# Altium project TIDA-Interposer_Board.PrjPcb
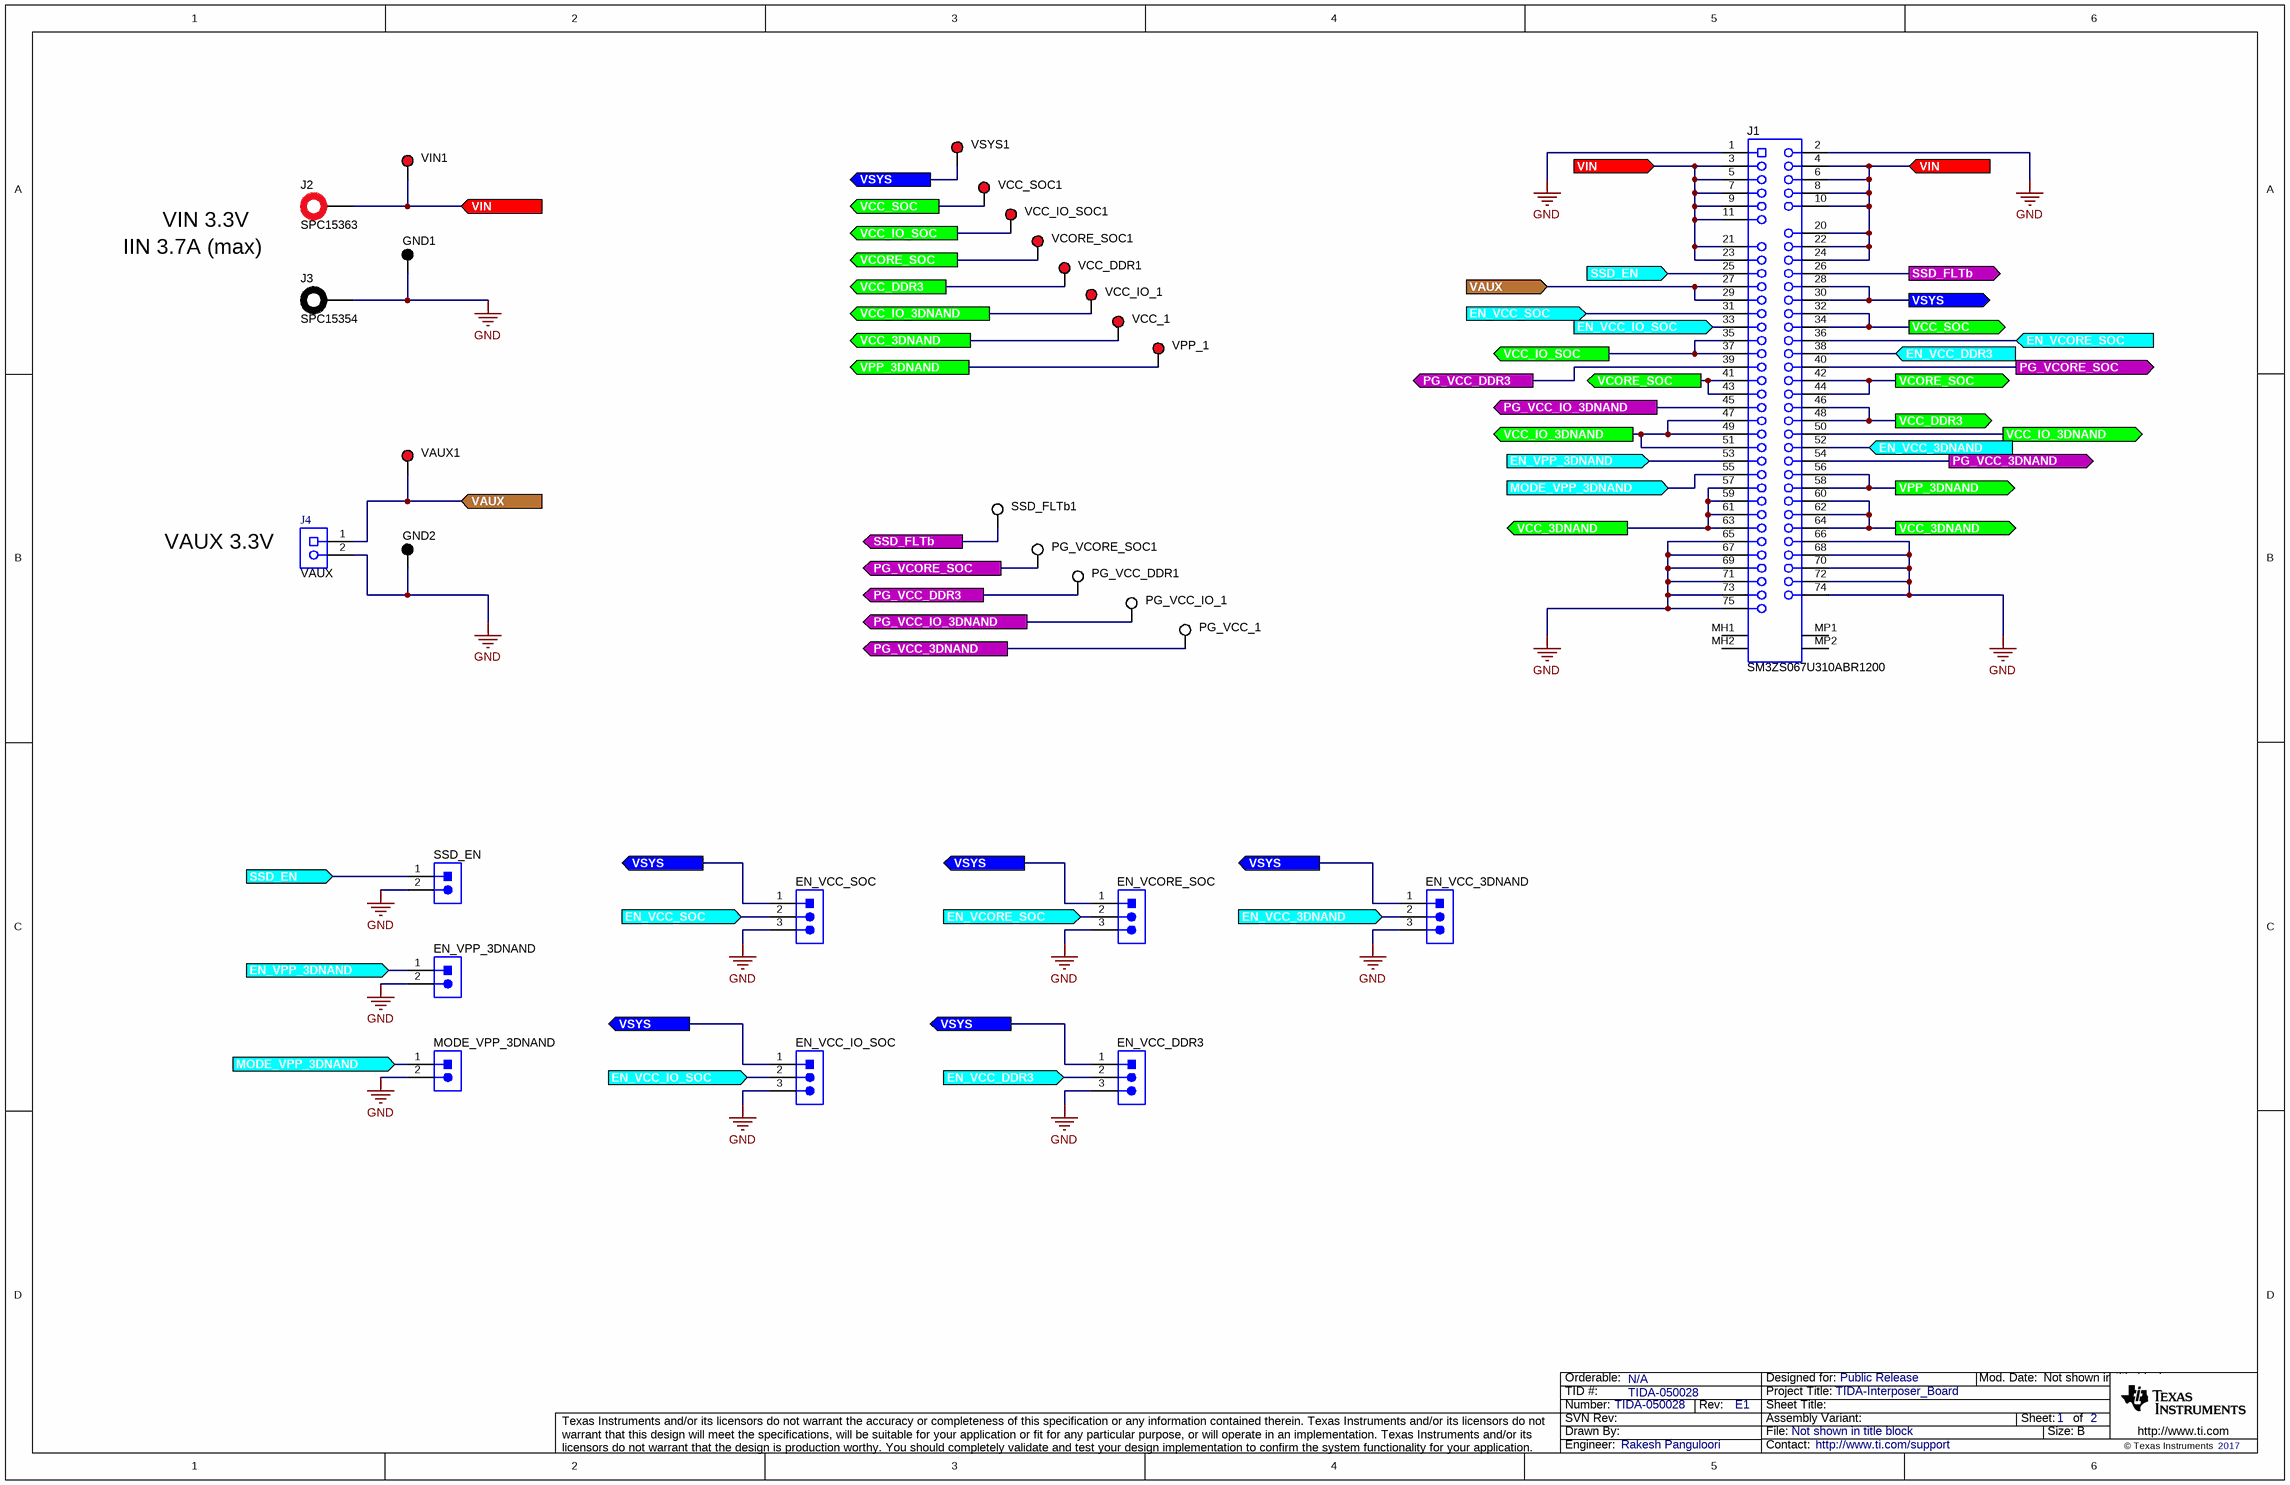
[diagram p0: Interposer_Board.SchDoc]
CopyrightYear: 2017; PCB_Layout: Tessolve; PCB_Rev: E1; PRJ_Customer: Public Release; PRJ_Engineer: Rakesh Panguloori; PRJ_Number: TIDA-050028; PRJ_Title: TIDA-Interposer_Board; SCH_Rev: E1; TechSupport: http://www.ti.com/support; TID: TIDA-050028
2 sheets, 56 parts. Net scope: flat (ports and power ports of the same name join across sheets).
Board file: TIDA-Interposer_Board_PCB.PcbDoc
Sheets:
  Interposer_Board.SchDoc
  EVM_Hardware.SchDoc

## Sheet Interposer_Board.SchDoc
size 431 x 279 mm; Date: Not shown in title block; ApprovedBy: Not shown in title block; CheckedBy: Not shown in title block; Author: Not shown in title block; CompanyName: Not shown in title block; Engineer: Not shown in title block; Organization: Not shown in title block; Address1: Not shown in title block; Address2: Not shown in title block; Address3: Not shown in title block; Address4: Not shown in title block; DocumentNumber: 1; Revision: Use project parameter SCH_Rev; SheetNumber: 1; SheetTotal: 2; PageSetup: Record=PageOptions¦CenterHorizontal=True¦CenterVertical=True¦PrintScale=1.00¦XCorrection=1.00¦YCorrection=1.00¦PrintKind=0¦BorderSize=5000000¦LeftOffset=0¦BottomOffset=0¦Orientation=2¦PaperLength=1000¦PaperWidth=1000¦Scale=100¦PaperSource=15¦PrintQuality=600¦MediaType=1¦DitherType=10¦PaperKind=Letter¦PrintScaleMode=1; EVM_Orderable: N/A

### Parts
EN_VCC_3DNAND  (no value)  [Samtec_TSW-103-07-T-S]
EN_VCC_DDR3  (no value)  [Samtec_TSW-103-07-T-S]
EN_VCC_IO_SOC  (no value)  [Samtec_TSW-103-07-T-S]
EN_VCC_SOC  (no value)  [Samtec_TSW-103-07-T-S]
EN_VCORE_SOC  (no value)  [Samtec_TSW-103-07-T-S]
EN_VPP_3DNAND  (no value)  [Samtec_TSW-102-07-T-S]
GND1  (no value)  [Keystone5006]
GND2  (no value)  [Keystone5006]
J1  SM3ZS067U310ABR1200  [JAE_SM3ZS067U310ABR1200]
J2  SPC15363  [Tenma_SPC15363]
J3  SPC15354  [Tenma_SPC15354]
J4  VAUX  [TEC_282841-2]
MODE_VPP_3DNAND  (no value)  [Samtec_TSW-102-07-T-S]
PG_VCC_1  (no value)  [Keystone5002]
PG_VCC_DDR1  (no value)  [Keystone5002]
PG_VCC_IO_1  (no value)  [Keystone5002]
PG_VCORE_SOC1  (no value)  [Keystone5002]
SSD_EN  (no value)  [Samtec_TSW-102-07-T-S]
SSD_FLTb1  (no value)  [Keystone5002]
VAUX1  (no value)  [Keystone5000]
VCC_1  (no value)  [Keystone5000]
VCC_DDR1  (no value)  [Keystone5000]
VCC_IO_1  (no value)  [Keystone5000]
VCC_IO_SOC1  (no value)  [Keystone5000]
VCC_SOC1  (no value)  [Keystone5000]
VCORE_SOC1  (no value)  [Keystone5000]
VIN1  (no value)  [Keystone5000]
VPP_1  (no value)  [Keystone5000]
VSYS1  (no value)  [Keystone5000]

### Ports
EN_VCC_3DNAND (in), EN_VCC_DDR3 (in), EN_VCC_IO_SOC (in), EN_VCC_SOC (in), EN_VCORE_SOC (in), EN_VPP_3DNAND (in), MODE_VPP_3DNAND (in), PG_VCC_3DNAND (out), PG_VCC_DDR3 (out), PG_VCC_IO_3DNAND (out), PG_VCORE_SOC (out), SSD_EN (in), SSD_FLTb (out), VAUX (in), VCC_3DNAND (out), VCC_DDR3 (out), VCC_IO_3DNAND (out), VCC_IO_SOC (out), VCC_SOC (out), VCORE_SOC (out), VIN (in), VPP_3DNAND (out), VSYS (out)

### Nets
GND: EN_VCC_3DNAND.3 EN_VCC_DDR3.3 EN_VCC_IO_SOC.3 EN_VCC_SOC.3 EN_VCORE_SOC.3 EN_VPP_3DNAND.2 GND1.1 GND2.1 J1.1 J1.2 J1.65 J1.66 J1.67 J1.68 J1.69 J1.70 J1.71 J1.72 J1.73 J1.74 J1.75 J3.1 J4.2 MODE_VPP_3DNAND.2 SSD_EN.2
EN_VCC_3DNAND: EN_VCC_3DNAND.2 J1.52 ; port EN_VCC_3DNAND
EN_VCC_DDR3: EN_VCC_DDR3.2 J1.38 ; port EN_VCC_DDR3
EN_VCC_IO_SOC: EN_VCC_IO_SOC.2 J1.33 ; port EN_VCC_IO_SOC
EN_VCC_SOC: EN_VCC_SOC.2 J1.31 ; port EN_VCC_SOC
EN_VCORE_SOC: EN_VCORE_SOC.2 J1.36 ; port EN_VCORE_SOC
EN_VPP_3DNAND: EN_VPP_3DNAND.1 J1.53 ; port EN_VPP_3DNAND
MODE_VPP_3DNAND: J1.55 MODE_VPP_3DNAND.1 ; port MODE_VPP_3DNAND
PG_VCC_3DNAND: J1.54 PG_VCC_1.1 ; port PG_VCC_3DNAND
PG_VCC_DDR3: PG_VCC_DDR1.1 ; port PG_VCC_DDR3
PG_VCC_IO_3DNAND: J1.45 PG_VCC_IO_1.1 ; port PG_VCC_IO_3DNAND
PG_VCORE_SOC: J1.40 PG_VCORE_SOC1.1 ; port PG_VCORE_SOC
SSD_EN: J1.25 SSD_EN.1 ; port SSD_EN
SSD_FLTb: J1.26 SSD_FLTb1.1 ; port SSD_FLTb
VAUX: J1.27 J1.29 J4.1 VAUX1.1 ; port VAUX
VCC_3DNAND: J1.60 J1.62 J1.64 VCC_1.1 ; port VCC_3DNAND
VCC_DDR3: J1.46 J1.48 VCC_DDR1.1 ; port VCC_DDR3
VCC_IO_3DNAND: J1.47 J1.49 J1.50 J1.51 VCC_IO_1.1 ; port VCC_IO_3DNAND
VCC_IO_SOC: J1.35 J1.37 VCC_IO_SOC1.1 ; port VCC_IO_SOC
VCC_SOC: J1.32 J1.34 VCC_SOC1.1 ; port VCC_SOC
VCORE_SOC: J1.41 J1.42 J1.43 J1.44 VCORE_SOC1.1 ; port VCORE_SOC
VIN: J1.3 J1.4 J1.5 J1.6 J1.7 J1.8 J1.9 J1.10 J1.11 J1.20 J1.21 J1.22 J1.23 J1.24 J2.1 VIN1.1 ; port VIN
VPP_3DNAND: J1.56 J1.58 VPP_1.1 ; port VPP_3DNAND
VSYS: EN_VCC_3DNAND.1 EN_VCC_DDR3.1 EN_VCC_IO_SOC.1 EN_VCC_SOC.1 EN_VCORE_SOC.1 J1.28 J1.30 VSYS1.1 ; port VSYS
NetJ1_57: J1.57 J1.59 J1.61 J1.63

Not connected (* = marked no-connect by the designer): J1 39 MH1 MH2 MP1 MP2

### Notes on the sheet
- VIN 3.3V
- IIN 3.7A (max)
- VAUX 3.3V

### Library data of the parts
EN_VCC_3DNAND EN_VCC_DDR3 EN_VCC_IO_SOC EN_VCC_SOC EN_VCORE_SOC = CMP-0075530-2: Header, 2.54 mm, 3x1, Tin, TH; PartNumber: TSW-103-07-T-S; Manufacturer: Samtec; Pitch_mm: 2.54; Cert_VDE: N; Gender: Male; Cert_CSA: Y; Voltage_V: 550V; Green_REACh: Passed; Current_A: 6.3A; Green_Lifecycle: Active; Row_Count: 1
EN_VPP_3DNAND MODE_VPP_3DNAND SSD_EN = CMP-0075508-2: Header, 2.54 mm, 2x1, Tin, TH; PartNumber: TSW-102-07-T-S; Manufacturer: Samtec; Pitch_mm: 2.54; Cert_VDE: N; Gender: Male; Cert_CSA: Y; Voltage_V: 550V; Green_REACh: Passed; Current_A: 6.3A; Green_Lifecycle: Active; Row_Count: 1
GND1 GND2 = CMP-0055143-1: Test Point, Compact, Black, TH; Manufacturer: Keystone; PartNumber: 5006; CNHeader: FALSE; Green_Lifecycle: Active; Green_REACh: Passed; ContactFinish: Silver; CT: TRUE
J1 = CMP-0075070-1: PCI Express M.2 connector, 0.5mm, B Key, Gold, R/A, SMD; Manufacturer: JAE Electronics; CT: False
J2 = CMP-0055399-2: BANANA JACK, SOLDER LUG, RED, TH; Manufacturer: Tenma; CNHeader: FALSE; Green_Lifecycle: Not Set; Green_REACh: Incomplete; CT: TRUE
J3 = CMP-0055398-2: BANANA JACK, SOLDER LUG, BLACK, TH; Manufacturer: Tenma; CNHeader: FALSE; Green_Lifecycle: Not Set; Green_REACh: Incomplete; CT: TRUE
J4 = CMP-0054973-1: Terminal Block, 2x1, 5.08mm, TH; Manufacturer: TE Connectivity; PartNumber: 282841-2; CNHeader: FALSE; Green_Lifecycle: Active; Green_REACh: Passed; CT: TRUE
PG_VCC_1 PG_VCC_DDR1 PG_VCC_IO_1 PG_VCORE_SOC1 SSD_FLTb1 = CMP-0055139-1: Test Point, Miniature, White, TH; Manufacturer: Keystone; PartNumber: 5002; CNHeader: FALSE; Green_Lifecycle: Active; Green_REACh: Passed; ContactFinish: Silver; CT: TRUE
VAUX1 VCC_1 VCC_DDR1 VCC_IO_1 VCC_IO_SOC1 VCC_SOC1 VCORE_SOC1 VIN1 VPP_1 VSYS1 = CMP-0055137-1: Test Point, Miniature, Red, TH; Manufacturer: Keystone; PartNumber: 5000; CNHeader: FALSE; Green_Lifecycle: Active; Green_REACh: Passed; ContactFinish: Silver; CT: TRUE

## Sheet EVM_Hardware.SchDoc
size 431 x 279 mm; Date: Not shown in title block; ApprovedBy: Not shown in title block; CheckedBy: Not shown in title block; Author: Not shown in title block; CompanyName: Not shown in title block; Engineer: Not shown in title block; Organization: Not shown in title block; Address1: Not shown in title block; Address2: Not shown in title block; Address3: Not shown in title block; Address4: Not shown in title block; DocumentNumber: 1; Revision: Use project parameter SCH_Rev; SheetNumber: 2; SheetTotal: 2; PageSetup: Record=PageOptions¦CenterHorizontal=True¦CenterVertical=True¦PrintScale=1.00¦XCorrection=1.00¦YCorrection=1.00¦PrintKind=0¦BorderSize=5000000¦LeftOffset=0¦BottomOffset=0¦Orientation=2¦PaperLength=1000¦PaperWidth=1000¦Scale=100¦PaperSource=15¦PrintQuality=600¦MediaType=1¦DitherType=10¦PaperKind=Letter¦PrintScaleMode=1; EVM_Orderable: N/A
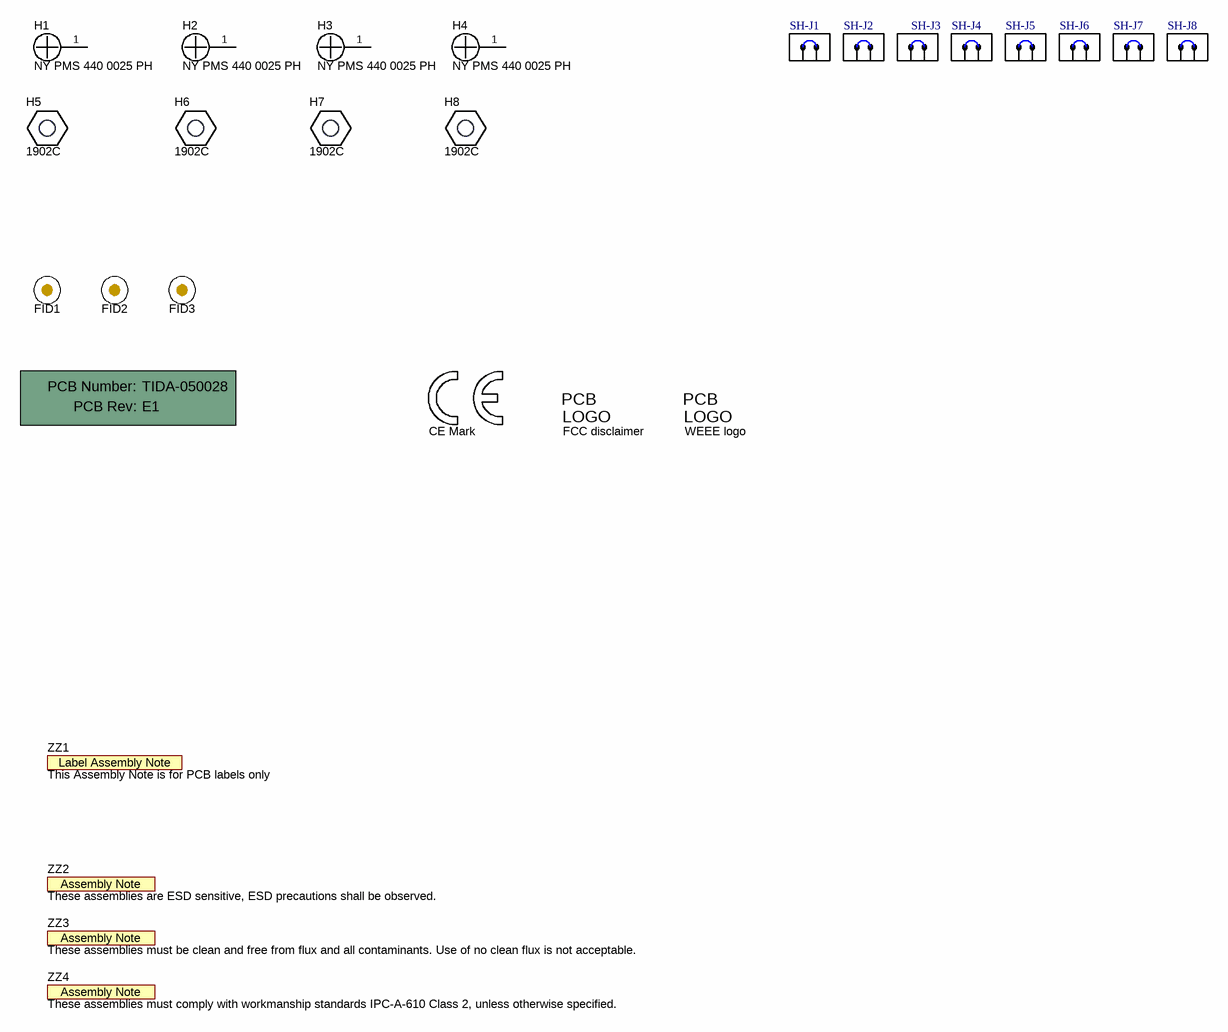
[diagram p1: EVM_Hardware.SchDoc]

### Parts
!PCB1  Printed Circuit Board  (value not drawn)  (mechanical)
FID1  Fiducial  [Fiducial10-20]  (value not drawn)
FID2  Fiducial  [Fiducial10-20]  (value not drawn)
FID3  Fiducial  [Fiducial10-20]  (value not drawn)
H1  NY PMS 440 0025 PH  [NY PMS 440 0025 PH]
H2  NY PMS 440 0025 PH  [NY PMS 440 0025 PH]
H3  NY PMS 440 0025 PH  [NY PMS 440 0025 PH]
H4  NY PMS 440 0025 PH  [NY PMS 440 0025 PH]
H5  1902C  [Keystone_1902C]
H6  1902C  [Keystone_1902C]
H7  1902C  [Keystone_1902C]
H8  1902C  [Keystone_1902C]
Logo1  CE Mark  [CE_Mark_5mm]  (no BOM)
Logo3  FCC disclaimer  [FCC_disclaimer]  (no BOM)
Logo4  WEEE logo  [WEEE_Minimum]  (no BOM)
SH-J1  969102-0000-DA  [SNT-100-BK-G]  (value not drawn)
SH-J2  969102-0000-DA  [SNT-100-BK-G]  (value not drawn)
SH-J3  969102-0000-DA  [SNT-100-BK-G]  (value not drawn)
SH-J4  969102-0000-DA  [SNT-100-BK-G]  (value not drawn)
SH-J5  969102-0000-DA  [SNT-100-BK-G]  (value not drawn)
SH-J6  969102-0000-DA  [SNT-100-BK-G]  (value not drawn)
SH-J7  969102-0000-DA  [SNT-100-BK-G]  (value not drawn)
SH-J8  969102-0000-DA  [SNT-100-BK-G]  (value not drawn)
ZZ1  This Assembly Note is for PCB labels only  [AssemblyNoteLabel]  (no BOM)
ZZ2  These assemblies are ESD sensitive, ESD precautions shall be observed.  [AssemblyNote]  (no BOM)
ZZ3  These assemblies must be clean and free from flux and all contaminants. Use of no clean flux is not acceptable.  [AssemblyNote]  (no BOM)
ZZ4  These assemblies must comply with workmanship standards IPC-A-610 Class 2, unless otherwise specified.  [AssemblyNote]  (no BOM)

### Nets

Not connected (* = marked no-connect by the designer): H1 1; H2 1; H3 1; H4 1

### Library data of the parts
!PCB1 = CMP-0003618-2: Manufacturer: Any; PartNumber: TIDA-050028
FID1-FID3 = CMP-0077181-1: Fiducial mark.  There is nothing to buy or mount.
H1-H4 = CMP-0003617-1: Machine Screw, Round, #4-40 x 1/4, Nylon, Philips panhead; Manufacturer: B&F Fastener Supply; CompType: Hardware
H5-H8 = CMP-0003610-1: Standoff, Hex, 0.5"L #4-40 Nylon; Manufacturer: Keystone; CompType: Hardware
Logo1 = CMP-0074844-1: SymbolCreator: a0412235
Logo3 = CMP-0074847-1: FCC_disclaimer; Library Reference: Logo
Logo4 = CMP-0074769-1
SH-J1-SH-J8 = CMP-0003614-1: Shunt, 100mil, Gold plated, Black; Alternate Manufacturer: Samtec; Manufacturer: 3M; Note: You can "mate" this to a header by matching the designator.  i.e. use SH-J3 for header J3; Value: 1x2
ZZ1 = CMP-0003616-3
ZZ2 = CMP-0077236-1
ZZ3 = CMP-0077237-1
ZZ4 = CMP-0077238-1

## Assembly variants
001: all parts fitted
